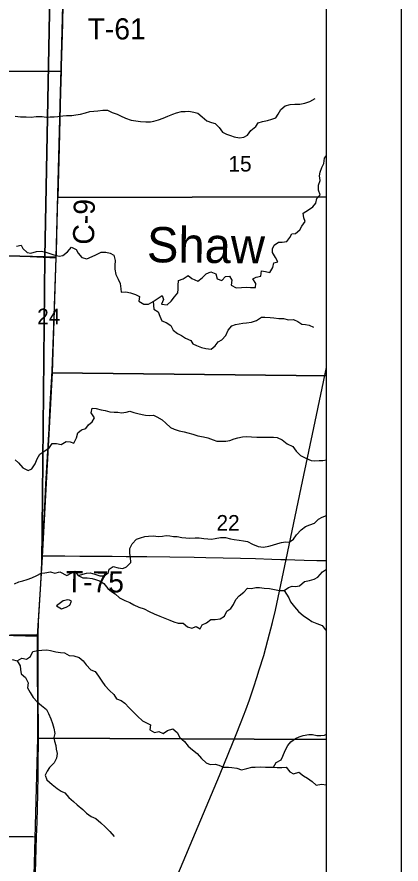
# Model space of a CAD drawing. Extents: x 0 to 34, y 0 to 22.
# Drawn here: x 7.968 to 9, y 17.017 to 19.29 of the extents above; entities that cross this region are included whole.
import ezdxf

# ---------------------------------------------------------------- set-up
doc = ezdxf.new("R2010")
doc.units = 0
for name, color, linetype in [('Default', 7, 'Continuous'), ('GM_X_City_Street', 7, 'Continuous'), ('GM_X_Corporation', 7, 'Continuous'), ('GM_X_County_Road_Text', 7, 'Continuous'), ('GM_X_Interchange_Ramps', 7, 'Continuous'), ('GM_X_Major_River', 7, 'Continuous'), ('GM_X_Major_River_Text', 7, 'Continuous'), ('GM_X_Minor_River', 7, 'Continuous'), ('GM_X_Minor_River_Text', 7, 'Continuous'), ('GM_X_Section', 7, 'Continuous'), ('GM_X_Unincorporated_Location', 7, 'Continuous'), ('SH_Cut_Line', 7, 'Continuous'), ('SH_Text', 7, 'Continuous')]:
    doc.layers.add(name, color=color, linetype=linetype)

msp = doc.modelspace()

# ---------------------------------------------------------------- linework, layer by layer
at = {"layer": 'Default'}
for points in [[(8.0916, 19.3249), (8.0903, 19.2721), (8.0872, 19.1572), (8.0868, 19.1446), (8.0851, 19.0888), (8.0831, 19.0143), (8.0812, 18.9398), (8.0776, 18.8052), (8.8, 18.8069), (8.8, 20.8)], [(7.0025, 16.32), (7.0145, 17.1525), (7.0215, 17.6587), (7.0359, 18.6717), (7.042, 19.1437), (8.0868, 19.1446), (8.0872, 19.1572), (8.0903, 19.2721), (8.0916, 19.3249)], [(8.8, 14), (8.8, 18.8069), (8.0776, 18.8052), (8.0812, 18.9398), (8.0831, 19.0143), (8.0851, 19.0888), (8.0868, 19.1446), (7.042, 19.1437), (7.0359, 18.6717), (7.0215, 17.6587), (7.0145, 17.1525), (7.0025, 16.32)]]:
    msp.add_lwpolyline(points, dxfattribs=at)
for points in [[(8.8, 18.3267), (8.8, 19.3242), (8.0902, 19.3206), (8.0725, 18.6456), (8.0624, 18.3353)], [(8.8, 17.3506), (8.8, 18.3267), (8.0624, 18.3353), (8.0346, 17.8251), (8.0227, 17.628), (8.0236, 17.3548)], [(8.8, 16.334), (8.8, 17.3506), (8.0236, 17.3548), (8.0033, 16.6164), (7.9948, 16.3527)]]:
    msp.add_lwpolyline(points, close=True, dxfattribs=at)
at = {"layer": 'GM_X_City_Street'}
for points in [[(8.0736, 18.6435), (8.0739, 18.6535), (8.0751, 18.7032), (8.0778, 18.8047), (8.0814, 18.9392), (8.0833, 19.0138), (8.0854, 19.0883), (8.087, 19.1441), (8.0874, 19.1566), (8.0905, 19.2715), (8.0918, 19.3243), (8.0919, 19.3282)], [(7.0361, 18.6712), (7.0817, 18.6703), (7.1624, 18.6687), (7.2183, 18.6674), (7.2742, 18.6663), (7.3115, 18.6656), (7.3705, 18.6642), (7.4326, 18.6629), (7.4885, 18.6619), (7.5941, 18.6594), (7.6531, 18.6577), (7.7773, 18.6538), (7.8239, 18.6526), (7.9854, 18.6475), (8.0568, 18.6446), (8.0661, 18.644), (8.0736, 18.6435)], [(8.0356, 17.8442), (8.0369, 17.8684), (8.0428, 17.977), (8.0459, 18.0359), (8.0542, 18.1848), (8.0576, 18.25), (8.0625, 18.3399), (8.0663, 18.4362), (8.0709, 18.5666), (8.0736, 18.6435)], [(8.0248, 17.6315), (8.0262, 17.6667), (8.0318, 17.7691), (8.0356, 17.8442)], [(7.9517, 17.633), (8.0045, 17.6318), (8.0225, 17.6315), (8.0248, 17.6315)], [(8.021, 17.0901), (8.0222, 17.1294), (8.0239, 17.2039), (8.0248, 17.2567), (8.026, 17.3779), (8.0255, 17.4618), (8.025, 17.5488), (8.0248, 17.6295), (8.0248, 17.6315)], [(7.9302, 17.0909), (7.9737, 17.0906), (7.9985, 17.0906), (8.0109, 17.0903), (8.0181, 17.0901), (8.021, 17.0901)], [(7.9989, 16.356), (8.0025, 16.468), (8.0046, 16.5332), (8.0075, 16.6325), (8.0103, 16.7226), (8.0122, 16.7909), (8.0126, 16.8127), (8.0141, 16.8748), (8.017, 16.9617), (8.021, 17.0901)]]:
    msp.add_lwpolyline(points, dxfattribs=at)
at = {"layer": 'GM_X_Corporation'}
msp.add_lwpolyline([(8.3889, 16.9613), (8.4405, 17.0841), (8.5118, 17.2545), (8.5374, 17.3165), (8.5555, 17.3599), (8.5707, 17.398), (8.5828, 17.4305), (8.5926, 17.4578), (8.6048, 17.4925), (8.6127, 17.5173), (8.6192, 17.5381), (8.6309, 17.576), (8.6422, 17.6172), (8.6544, 17.6645), (8.6624, 17.6979), (8.6914, 17.834), (8.7316, 18.026), (8.7694, 18.2043), (8.8, 18.3493)], dxfattribs=at)
at = {"layer": 'GM_X_Interchange_Ramps'}
msp.add_lwpolyline([(8.0356, 17.8442), (8.0392, 17.8442), (8.0623, 17.8442), (8.0964, 17.8438), (8.1367, 17.8433), (8.1865, 17.8427), (8.2238, 17.8425), (8.2611, 17.8421), (8.317, 17.8417), (8.3792, 17.8408), (8.4444, 17.8398), (8.4755, 17.8392), (8.5221, 17.8386), (8.5687, 17.838), (8.6091, 17.8365), (8.6526, 17.835), (8.6774, 17.8343), (8.693, 17.8338), (8.7147, 17.8331), (8.7395, 17.8324), (8.7737, 17.8316), (8.8, 17.8309)], dxfattribs=at)
at = {"layer": 'GM_X_Major_River'}
for points in [[(8.1088, 17.7245), (8.105, 17.726), (8.0924, 17.7229), (8.0745, 17.71)], [(8.0745, 17.71), (8.0878, 17.702), (8.1004, 17.7062), (8.1099, 17.7115), (8.1148, 17.7222), (8.1088, 17.7245)]]:
    msp.add_lwpolyline(points, dxfattribs=at)
at = {"layer": 'GM_X_Section'}
for points in [[(8.4537, 19.0313), (8.4659, 19.0221), (8.478, 19.0115), (8.491, 19.0062), (8.5005, 19.0035), (8.5111, 18.9932), (8.5202, 18.9811), (8.5309, 18.975), (8.5415, 18.972), (8.5518, 18.9682), (8.5655, 18.9655), (8.5777, 18.967), (8.5876, 18.9727), (8.5963, 18.9852), (8.6096, 18.9962), (8.6165, 19.0057), (8.6275, 19.0095), (8.6408, 19.0118), (8.6526, 19.016), (8.6637, 19.019), (8.6694, 19.0293), (8.677, 19.0418), (8.6884, 19.0517), (8.7021, 19.0547), (8.7143, 19.0555), (8.728, 19.0562), (8.7417, 19.0581), (8.7546, 19.0631), (8.7691, 19.0707)], [(7.963, 19.0238), (7.9778, 19.0219), (7.9926, 19.0219), (8.006, 19.0208), (8.0193, 19.0227), (8.036, 19.0223), (8.0463, 19.0211), (8.0577, 19.0215), (8.0676, 19.0219), (8.0775, 19.0227), (8.0915, 19.0246), (8.1014, 19.0253), (8.1159, 19.0253), (8.1265, 19.0272), (8.1387, 19.0291), (8.152, 19.0325), (8.1642, 19.0359), (8.1745, 19.0367), (8.1851, 19.0382), (8.1988, 19.0401), (8.211, 19.0393), (8.2243, 19.0336), (8.2369, 19.0287), (8.2464, 19.0241), (8.2601, 19.018), (8.2753, 19.0131), (8.2878, 19.0108), (8.3004, 19.0089), (8.3141, 19.0081), (8.3266, 19.0085), (8.3361, 19.0104), (8.3487, 19.0142), (8.3609, 19.0184), (8.3734, 19.0233), (8.3864, 19.0286), (8.3966, 19.0324), (8.4099, 19.0362), (8.4202, 19.0362), (8.4297, 19.0373), (8.443, 19.0347), (8.4537, 19.0313)], [(8.7712, 18.7906), (8.7735, 18.8028), (8.7822, 18.8127), (8.7781, 18.8248), (8.7781, 18.8389), (8.7826, 18.8514), (8.7807, 18.8636), (8.7823, 18.8731), (8.7872, 18.886), (8.7926, 18.8966), (8.7945, 18.9107), (8.8, 18.9178)], [(8.3621, 18.5321), (8.3568, 18.5195), (8.3713, 18.5176), (8.3823, 18.5275), (8.3914, 18.5389), (8.4006, 18.5495), (8.401, 18.559), (8.401, 18.5693), (8.4025, 18.5826), (8.4147, 18.5868), (8.4284, 18.5959), (8.4379, 18.5883), (8.4542, 18.5807), (8.4656, 18.5898), (8.4767, 18.6004), (8.4888, 18.6061), (8.5025, 18.6004), (8.5063, 18.5875), (8.5181, 18.5829), (8.5284, 18.5932), (8.5387, 18.5947), (8.5451, 18.5837), (8.5436, 18.5704), (8.5569, 18.5632), (8.5714, 18.5639), (8.5839, 18.5647), (8.5953, 18.5639), (8.6087, 18.5639), (8.6094, 18.5745), (8.6014, 18.5875), (8.6109, 18.5913), (8.6235, 18.5947), (8.6254, 18.6083), (8.6361, 18.6064), (8.6475, 18.6042), (8.6551, 18.6174), (8.6581, 18.6304), (8.6692, 18.633), (8.6627, 18.6448), (8.6543, 18.6581), (8.6544, 18.668), (8.6593, 18.6775), (8.6707, 18.6858), (8.681, 18.6858), (8.6928, 18.6873), (8.7015, 18.6984), (8.7061, 18.7082), (8.7168, 18.7086), (8.7278, 18.7189), (8.7335, 18.7284), (8.7426, 18.7413), (8.7388, 18.7508), (8.7369, 18.7637), (8.751, 18.7724), (8.7632, 18.78), (8.7712, 18.7906)], [(7.967, 18.6751), (7.9791, 18.6777), (7.9841, 18.6682), (7.9955, 18.6576), (8.0058, 18.6557), (8.0202, 18.6602), (8.0328, 18.6617), (8.0453, 18.6591), (8.056, 18.6549), (8.067, 18.6515), (8.0815, 18.6477), (8.091, 18.6496), (8.1035, 18.6594), (8.1149, 18.672), (8.1271, 18.6655), (8.1321, 18.6556), (8.1427, 18.6446), (8.156, 18.6408), (8.1697, 18.6469), (8.1796, 18.6514), (8.1944, 18.659), (8.207, 18.659), (8.2188, 18.656), (8.2283, 18.6507), (8.2317, 18.6362), (8.2309, 18.6233), (8.2309, 18.613), (8.234, 18.5986), (8.2397, 18.5861), (8.2454, 18.5747), (8.2473, 18.5606), (8.2484, 18.5511), (8.261, 18.5519), (8.2728, 18.5496), (8.2864, 18.5454), (8.2975, 18.5401), (8.2956, 18.5275), (8.3085, 18.5192), (8.3214, 18.5195), (8.334, 18.526), (8.3583, 18.5427), (8.3621, 18.5321)], [(8.334, 18.526), (8.3355, 18.5055), (8.3473, 18.4983), (8.3522, 18.4865), (8.3572, 18.4743), (8.3693, 18.4701), (8.3819, 18.4618), (8.388, 18.4492), (8.399, 18.4405), (8.41, 18.4352), (8.421, 18.428), (8.4351, 18.4219), (8.4404, 18.4124), (8.4503, 18.4086), (8.464, 18.4032), (8.4758, 18.3998), (8.4899, 18.3987), (8.5005, 18.4074), (8.5089, 18.4177), (8.5184, 18.423), (8.5291, 18.4355), (8.5352, 18.4496), (8.5455, 18.461), (8.5553, 18.4648), (8.5751, 18.4678), (8.5846, 18.4693), (8.598, 18.4712), (8.6113, 18.475), (8.6246, 18.4841), (8.6341, 18.4841), (8.6482, 18.4837), (8.6584, 18.4822), (8.6718, 18.481), (8.6839, 18.4803), (8.6972, 18.4772), (8.7106, 18.4784), (8.7227, 18.4727), (8.7334, 18.4658), (8.7433, 18.4647), (8.7528, 18.4628), (8.7649, 18.4571)], [(7.9629, 18.1014), (7.9724, 18.0938), (7.9842, 18.0801), (7.9979, 18.0725), (8.0078, 18.0774), (8.0169, 18.0907), (8.0222, 18.104), (8.0295, 18.1166), (8.0428, 18.1257), (8.0553, 18.1344), (8.0629, 18.145), (8.0747, 18.1454), (8.0869, 18.1428), (8.1006, 18.1503), (8.1109, 18.1496), (8.1208, 18.1462), (8.1276, 18.1602), (8.1314, 18.1735), (8.1413, 18.1819), (8.1535, 18.1853), (8.1607, 18.1952), (8.1703, 18.2035), (8.176, 18.2138), (8.1672, 18.2278), (8.1699, 18.2404), (8.1805, 18.2392), (8.1946, 18.2354), (8.2049, 18.2339), (8.2174, 18.2301), (8.2296, 18.2293), (8.2391, 18.2297), (8.2486, 18.2274), (8.2619, 18.2293), (8.2715, 18.2316), (8.2825, 18.2285), (8.2928, 18.2259), (8.3042, 18.2228), (8.3137, 18.2213), (8.3239, 18.2205), (8.3346, 18.2213), (8.3441, 18.2171), (8.3578, 18.2084)], [(8.3578, 18.2084), (8.3677, 18.1996), (8.381, 18.1882), (8.3905, 18.1841), (8.4034, 18.1795), (8.4171, 18.1764), (8.4274, 18.1738), (8.4407, 18.1707), (8.4544, 18.1658), (8.4688, 18.1631), (8.481, 18.1608), (8.4955, 18.1551), (8.505, 18.1517), (8.5156, 18.1513), (8.5293, 18.1517), (8.5396, 18.1536), (8.5514, 18.1574), (8.5617, 18.1604), (8.5742, 18.1635), (8.5849, 18.1638), (8.5978, 18.1635), (8.6123, 18.1623), (8.6233, 18.1623), (8.6328, 18.1619), (8.6469, 18.1623), (8.6571, 18.1619), (8.6674, 18.1612), (8.6807, 18.1555), (8.694, 18.1448), (8.7089, 18.1372), (8.718, 18.1247), (8.7298, 18.1129), (8.7438, 18.106), (8.7587, 18.0992), (8.7686, 18.0984), (8.78, 18.0992), (8.7895, 18.0996), (8.8, 18.1013)], [(8.1324, 17.7909), (8.1548, 17.7974), (8.1647, 17.7985), (8.1777, 17.7947), (8.1906, 17.7898), (8.202, 17.7898), (8.2134, 17.7981), (8.2161, 17.8076), (8.2267, 17.8148), (8.2397, 17.8118), (8.2522, 17.8095), (8.2621, 17.8141), (8.2739, 17.8258), (8.2732, 17.8406), (8.2716, 17.8505), (8.2713, 17.8634), (8.2774, 17.876), (8.2895, 17.8885), (8.2998, 17.8919), (8.312, 17.8953), (8.3219, 17.8969), (8.3344, 17.8976), (8.3481, 17.8957), (8.3588, 17.8965), (8.3687, 17.8987), (8.3786, 17.8976), (8.3884, 17.8957), (8.3983, 17.8953), (8.4113, 17.893), (8.4219, 17.8923), (8.4329, 17.8915), (8.4466, 17.8922), (8.4573, 17.8922), (8.4702, 17.8907), (8.4805, 17.8896), (8.4908, 17.8888), (8.5007, 17.8907), (8.5151, 17.893), (8.528, 17.8926), (8.5421, 17.8896), (8.552, 17.8877), (8.5649, 17.8857), (8.5767, 17.8842), (8.5874, 17.8827), (8.6007, 17.8747), (8.6159, 17.869), (8.6304, 17.8675), (8.6444, 17.8698), (8.6543, 17.872), (8.6688, 17.8766), (8.6791, 17.8792), (8.6893, 17.8811), (8.6996, 17.8804), (8.711, 17.8884), (8.7194, 17.9001), (8.7312, 17.9134), (8.743, 17.9222), (8.7552, 17.9267), (8.7677, 17.9313), (8.778, 17.9423), (8.7883, 17.9476), (8.8, 17.9521)], [(7.9616, 17.769), (7.9734, 17.7739), (7.9836, 17.7769), (7.9954, 17.78), (8.008, 17.7845), (8.0213, 17.7913), (8.0331, 17.797), (8.0434, 17.7982), (8.0578, 17.8008), (8.07, 17.7974), (8.0829, 17.8012), (8.1019, 17.7906), (8.1134, 17.7974), (8.124, 17.8031), (8.1324, 17.7909), (8.1449, 17.7852), (8.1567, 17.7845), (8.1697, 17.7833), (8.1792, 17.7803), (8.1894, 17.7768), (8.2012, 17.7696), (8.2122, 17.7563), (8.2218, 17.748), (8.232, 17.7419), (8.2438, 17.7309), (8.2575, 17.7244), (8.2716, 17.7187), (8.2822, 17.7126), (8.2955, 17.7065), (8.31, 17.7012), (8.3237, 17.6947), (8.337, 17.6883), (8.3518, 17.6822), (8.3651, 17.6769), (8.3788, 17.6712), (8.3891, 17.667), (8.4016, 17.6632), (8.4142, 17.6628), (8.4264, 17.6537), (8.4382, 17.6495), (8.4499, 17.6544), (8.4606, 17.6483), (8.4655, 17.659), (8.4773, 17.6639), (8.4891, 17.6726)], [(8.4891, 17.6726), (8.5009, 17.673), (8.5142, 17.6745), (8.5257, 17.6821), (8.5318, 17.6954), (8.5424, 17.7023), (8.5496, 17.7133), (8.5565, 17.7266), (8.5649, 17.7368), (8.5774, 17.7467), (8.5877, 17.7573), (8.5984, 17.7566), (8.6098, 17.7585), (8.6193, 17.7588), (8.6322, 17.7569), (8.6463, 17.7558), (8.66, 17.7539), (8.6733, 17.7512), (8.6855, 17.7508), (8.6976, 17.7584), (8.7071, 17.7626), (8.7167, 17.7618), (8.7269, 17.7637), (8.7403, 17.7747), (8.7536, 17.7778), (8.7665, 17.7812), (8.7764, 17.7865), (8.7893, 17.8006), (8.7996, 17.8082), (8.8, 17.8083)], [(8.6855, 17.7508), (8.6988, 17.7314), (8.7033, 17.72), (8.7136, 17.7067), (8.7246, 17.6946), (8.7379, 17.6832), (8.7501, 17.6744), (8.76, 17.668), (8.7737, 17.6619), (8.7877, 17.6573), (8.7961, 17.6459), (8.8, 17.643)], [(7.9554, 17.5657), (7.9687, 17.5623), (7.9809, 17.5691), (7.9938, 17.5661), (8.0041, 17.5737), (8.0106, 17.587), (8.0243, 17.59), (8.0345, 17.5904), (8.0482, 17.5919), (8.0581, 17.5896), (8.0722, 17.5862), (8.0855, 17.5846), (8.0961, 17.5831), (8.1087, 17.5767), (8.1212, 17.5751), (8.1349, 17.5706), (8.1456, 17.5622), (8.1543, 17.5516), (8.1661, 17.5383), (8.1779, 17.5337), (8.187, 17.5212), (8.1958, 17.5075), (8.2041, 17.4957), (8.2167, 17.4824), (8.2285, 17.4714), (8.2357, 17.46), (8.2482, 17.4554), (8.2577, 17.4482), (8.2691, 17.436), (8.279, 17.4265), (8.2923, 17.4136), (8.3049, 17.4014), (8.3144, 17.3965), (8.3266, 17.39), (8.3247, 17.3767), (8.3372, 17.3695), (8.3494, 17.3725), (8.3608, 17.3668), (8.3726, 17.3752), (8.3867, 17.3798), (8.3981, 17.3699), (8.4057, 17.3566), (8.4178, 17.3452), (8.4281, 17.3334), (8.4395, 17.3235), (8.4524, 17.3136), (8.4642, 17.3003), (8.4764, 17.2885), (8.4867, 17.284), (8.5007, 17.2847), (8.5106, 17.2817), (8.5232, 17.2771), (8.5361, 17.2767), (8.5456, 17.2756), (8.5589, 17.2737), (8.5715, 17.2699), (8.5856, 17.2733), (8.5989, 17.2763), (8.6084, 17.2767), (8.6213, 17.2775), (8.6362, 17.2771), (8.6464, 17.2767), (8.6571, 17.2763), (8.667, 17.2759), (8.6799, 17.2755), (8.6909, 17.2767), (8.7008, 17.2645), (8.7111, 17.2592), (8.7252, 17.263), (8.7377, 17.2539), (8.7484, 17.2474), (8.7609, 17.2387), (8.7723, 17.2284), (8.7864, 17.2311), (8.8, 17.2295)], [(7.9687, 17.5623), (7.9763, 17.549), (7.9774, 17.5391), (7.9797, 17.5269), (7.9907, 17.5171), (7.9983, 17.5026), (7.9968, 17.4893), (8.0033, 17.4772), (8.0116, 17.4639), (8.0227, 17.4517), (8.0344, 17.4418), (8.0474, 17.4312), (8.0527, 17.4209), (8.0588, 17.4065), (8.0633, 17.3939), (8.0671, 17.381), (8.0698, 17.3673), (8.0667, 17.3563), (8.069, 17.3464), (8.0724, 17.3347), (8.0736, 17.3248), (8.0762, 17.3134), (8.0739, 17.3008), (8.0678, 17.2887), (8.0553, 17.2758), (8.0496, 17.2659), (8.0442, 17.2556), (8.048, 17.2423), (8.0625, 17.2302), (8.0762, 17.2195), (8.0865, 17.2127), (8.0967, 17.2081), (8.1077, 17.1956), (8.1203, 17.1842), (8.1302, 17.1754), (8.1454, 17.1629), (8.1549, 17.153), (8.1671, 17.1443), (8.18, 17.139), (8.1937, 17.1276), (8.2051, 17.1169), (8.2173, 17.104), (8.2294, 17.0903)], [(8.6571, 17.2763), (8.6643, 17.2888), (8.6776, 17.2968), (8.6822, 17.3063), (8.6887, 17.3215), (8.6959, 17.3352), (8.7039, 17.3451), (8.7165, 17.3538), (8.7263, 17.358), (8.7366, 17.3621), (8.7522, 17.364), (8.7617, 17.364), (8.7735, 17.3621), (8.7846, 17.3614), (8.7941, 17.3629), (8.8, 17.3653)]]:
    msp.add_lwpolyline(points, dxfattribs=at)
at = {"layer": 'GM_X_Unincorporated_Location'}
for points in [[(7.0617, 19.6888), (8.0628, 19.6744), (8.0433, 18.6458), (7.0397, 18.6727)], [(8.0628, 19.6744), (8.0709, 19.6746), (8.099, 19.6752), (8.0902, 19.3206), (8.0725, 18.6456), (8.064, 18.6456), (8.0433, 18.6458)], [(7.0397, 18.6727), (8.0433, 18.6458), (8.0346, 17.8251), (8.0227, 17.628), (7.0045, 17.6571)], [(8.0433, 18.6458), (8.064, 18.6456), (8.0725, 18.6456), (8.0624, 18.3353), (8.0346, 17.8251)], [(7.0045, 17.6571), (8.0227, 17.628), (8.0236, 17.3548), (8.0033, 16.6164), (7.0019, 16.6421)]]:
    msp.add_lwpolyline(points, close=True, dxfattribs=at)
at = {"layer": 'SH_Cut_Line'}
msp.add_line((9, 21), (9, 14), dxfattribs=at)
at = {"layer": 'SH_Text'}
msp.add_lwpolyline([(2.9377, 14), (8.8, 14), (8.8, 20.8), (2.9842, 20.8), (2.984, 20.7397), (2.9904, 20.3395), (2.9796, 19.7242), (2.9753, 18.7199), (2.9708, 17.6769), (2.9623, 15.7101), (2.9479, 14.7065)], close=True, dxfattribs=at)

# ---------------------------------------------------------------- texts
at = {"layer": 'GM_X_County_Road_Text'}
for s, rotation, p in [('T-61', 0, (8.1579, 19.2295)), ('T-75', 359.6422, (8.0992, 17.7463))]:
    msp.add_text(s, height=0.05682, rotation=rotation, dxfattribs=at).set_placement(p)
at = {"layer": 'GM_X_Major_River_Text'}
for s, p in [('15', (8.5362, 18.875)), ('24', (8.0225, 18.4652)), ('22', (8.5041, 17.9114))]:
    msp.add_text(s, height=0.04186, rotation=0, dxfattribs=at).set_placement(p)
at = {"layer": 'GM_X_Minor_River'}
msp.add_text('Shaw', height=0.09471, rotation=359.3539, dxfattribs=at).set_placement((8.3169, 18.6318))
at = {"layer": 'GM_X_Minor_River_Text'}
msp.add_text('C-9', height=0.05682, rotation=88.6259, dxfattribs=at).set_placement((8.1749, 18.6783))

doc.saveas('drawing.dxf')
